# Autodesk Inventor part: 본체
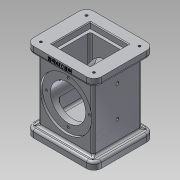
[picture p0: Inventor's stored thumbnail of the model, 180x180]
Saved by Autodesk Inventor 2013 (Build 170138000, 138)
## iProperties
Created: 2017-08
Part Number: 본체
Material: 알루미늄 6061
Document SubType Name: Modeling
Designer: Administrator
Density: 2.71 g/cm^3
Mass: 870.475 g
Surface Area: 647.043 cm^2
Volume: 321.208 cm^3
Author: Administrator
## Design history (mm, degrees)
sketch "스케치1"
  geometry: L1 (-46, -41)-(46, -41); L2 (46, -41)-(46, 41); L3 (46, 41)-(-46, 41); L4 (-46, 41)-(-46, -41); L5 (-46, -41)-(46, 41); L6 (46, -41)-(-46, 41); 1 further point
  constraints: 12 end point, 2 midpoint, 2 parallel, 1 horizontal, 1 perpendicular
  dimensions: "d0" = 92 distance of L3.end L2.end; "d1" = 82 distance of L2.end L1.end
extrude "돌출1" new body sketch "스케치1" distance "d2" = 10; taper "d3" = 0 deg
sketch "스케치2"
  geometry: L1 (-37, -33)-(37, -33); L2 (37, -33)-(37, 33); L3 (37, 33)-(-37, 33); L4 (-37, 33)-(-37, -33); L5 (-37, -33)-(37, 33); L6 (37, -33)-(-37, 33); 1 further point
  constraints: 12 end point, 2 midpoint, 2 parallel, 1 horizontal, 1 perpendicular
  dimensions: "d4" = 74 distance of L3.end L2.end; "d5" = 66 distance of L2.end L1.end
extrude "돌출2" join sketch "스케치2" distance "d6" = 88; taper "d7" = 0 deg
sketch "스케치3"
  geometry: L1 (-46, -41)-(46, -41); L2 (46, -41)-(46, 41); L3 (46, 41)-(-46, 41); L4 (-46, 41)-(-46, -41); L5 (-46, -41)-(46, 41); L6 (46, -41)-(-46, 41); 1 further point
  constraints: 12 end point, 2 midpoint, 2 parallel, 1 horizontal, 1 perpendicular
  dimensions: "d8" = 92 distance of L3.end L2.end; "d9" = 82 distance of L2.end L1.end
extrude "돌출3" join sketch "스케치3" distance "d10" = 10; taper "d11" = 0 deg
sketch "스케치4"
  geometry: L1 (-24, -24)-(24, -24); L2 (24, -24)-(24, 24); L3 (24, 24)-(-24, 24); L4 (-24, 24)-(-24, -24); L5 (-24, -24)-(24, 24); L6 (24, -24)-(-24, 24); 1 further point
  constraints: 12 end point, 2 midpoint, 2 parallel, 1 horizontal, 1 perpendicular
  dimensions: "d12" = 48 distance of L3.end L2.end; "d13" = 48 distance of L2.end L1.end
extrude "돌출4" cut sketch "스케치4" distance "d14" = 16; taper "d15" = 0 deg
sketch "스케치5"
  geometry: L1 (74, 0)-(0, 0) reference; L2 (74, 0)-(74, 88) reference; L3 (0, 88)-(74, 88) reference; L4 (0, 0)-(0, 88) reference; 1 further point
sketch "스케치6"
  geometry: L1 (-33, 10)-(33, 10) reference; L2 (-33, 10)-(-33, 98) reference; L3 (33, 98)-(-33, 98) reference; L4 (33, 10)-(33, 98) reference; L5 (-33, 89)-(-30, 89); L6 (-30, 89)-(-30, 78); L7 (-30, 78)-(30, 78); L8 (30, 78)-(30, 89); L9 (30, 89)-(33, 89); L10 (-33, 54)-(33, 54); L11 (41, 0)-(-41, 0) reference; L12 (-33, 89)-(-33, 54); L13 (33, 54)-(33, 89); L14 (33, 54)-(-33, 54); 1 further point
  constraints: 18 end point, 3 collinear, 3 perpendicular, 2 midpoint, 2 parallel, 2 point on line, 2 vertical alignment, 1 horizontal, 1 horizontal alignment
  dimensions: "d16" = 3 distance of L5.start L5.end; "d18" = 3 distance of L8.end L9.end; "d21" = 48 diameter of L7 L10; "d82" = 54 distance between parallel lines of L11 L10; "d83" = 35 distance between parallel lines of L5 L10
revolve "회전1" sketch "스케치6" stored, may be unused: angle "d22" = 90 deg
sketch "스케치7"
  geometry: L1 (-26, -26)-(26, -26); L2 (26, -26)-(26, 26); L3 (26, 26)-(-26, 26); L4 (-26, 26)-(-26, -26); L5 (-26, -26)-(26, 26); L6 (26, -26)-(-26, 26); 1 further point
  constraints: 12 end point, 2 midpoint, 2 parallel, 1 horizontal, 1 perpendicular
  dimensions: "d23" = 52 distance of L3.end L2.end; "d24" = 52 distance of L1.end L2.end
extrude "돌출5" cut sketch "스케치7" distance "d25" = 8; taper "d26" = 0 deg
sketch "스케치8"
  geometry: L1 (-22, -22)-(22, -22); L2 (22, -22)-(22, 22); L3 (22, 22)-(-22, 22); L4 (-22, 22)-(-22, -22); L5 (-22, -22)-(22, 22); L6 (22, -22)-(-22, 22); 1 further point
  constraints: 12 end point, 2 midpoint, 2 parallel, 1 horizontal, 1 perpendicular
  dimensions: "d27" = 44 distance of L3.end L2.end; "d28" = 44 distance of L2.end L1.end
extrude "돌출6" cut sketch "스케치8" distance "d29" = 74; taper "d30" = 0 deg
sketch "스케치9"
  geometry: L1 (-36, -31)-(36, -31); L2 (36, -31)-(36, 31); L3 (36, 31)-(-36, 31); L4 (-36, 31)-(-36, -31); L5 (-36, -31)-(36, 31); L6 (36, -31)-(-36, 31); 5 further points
  constraints: 12 end point, 4 coincident, 2 midpoint, 2 parallel, 1 horizontal, 1 perpendicular
  dimensions: "d31" = 72 distance of L3.end L2.end; "d32" = 62 distance of L2.end L1.end
hole "구멍1" sketch "스케치9" at (-36, 31), (36, 31), (36, -31), (-36, -31) diameter "d33" = 3.242; stored, may be unused: countersink angle "d37" = 90 deg, drill point angle "d39" = 118 deg; dims "d34" = 4, "d35" = 4, "d36" = 2, "d38" = 6
sketch "스케치10"
  geometry: L1 (-36, -31)-(36, -31); L2 (36, -31)-(36, 31); L3 (36, 31)-(-36, 31); L4 (-36, 31)-(-36, -31); L5 (-36, -31)-(36, 31); L6 (36, -31)-(-36, 31); 5 further points
  constraints: 12 end point, 4 coincident, 2 midpoint, 2 parallel, 1 horizontal, 1 perpendicular
  dimensions: "d40" = 72 distance of L3.end L2.end; "d41" = 62 distance of L2.end L1.end
hole "구멍2" sketch "스케치10" at (-36, 31), (36, 31), (36, -31), (-36, -31) diameter "d42" = 3.242; stored, may be unused: countersink angle "d46" = 90 deg, drill point angle "d48" = 118 deg; dims "d43" = 4, "d44" = 4, "d45" = 2, "d47" = 6
fillet "모깎기1" dims "d49" = 10
fillet "모깎기2" dims "d50" = 3
fillet "모깎기3" dims "d51" = 3
sketch "스케치11"
  geometry: L1 (0, 0)-(72, 0) reference; L2 (-10, 0)-(-10, -7) reference; 2 further points
  constraints: 1 other
  dimensions: "d52" = 46 distance from line of L2 point (36, -4); "d53" = 4 distance from line of L1 point (36, -4)
feature "엠보싱1" sketch "스케치11" dims "d0" = 92, "d1" = 82, "d8" = 92, "d9" = 82, "d54" = 0.5, "d55" = 0
fillet "모깎기4" dims "d56" = 3
chamfer "모따기1" distance "d57" = 1; stored, may be unused: second distance "d58" = 2, angle "d59" = 45 deg
sketch "스케치12" dims "d60" = 58
  geometry: C1 r 35 at (0, 0) reference; 3 further points
  constraints: 2 vertical alignment, 1 coincident, 2 other
hole "구멍3" sketch "스케치12" at (0, 29) diameter "d61" = 3.242; stored, may be unused: countersink angle "d65" = 90 deg, drill point angle "d67" = 118 deg; dims "d62" = 4, "d63" = 4, "d64" = 2, "d66" = 6
sketch "스케치13"
  geometry: L1 (13, -1)-(13, 61) reference; 4 further points
  constraints: 2 horizontal alignment, 1 midpoint
  dimensions: "d71" = 38 distance from line of L1 point (-25, 30); "d72" = 42 distance of point (-25, 30) point (-67, 30)
hole "구멍4" sketch "스케치13" at (-67, 30), (-25, 30) diameter "d73" = 4.134; stored, may be unused: countersink angle "d77" = 90 deg, drill point angle "d79" = 0 deg; dims "d74" = 30, "d75" = 4, "d76" = 2, "d78" = 30
fillet "모깎기5" dims "d80" = 3
fillet "모깎기6" dims "d81" = 3
node "솔리드1"
pattern_circular "원형 패턴1" dims angle "d69" = 360 deg
mirror "대칭1"
node "투영된 루프1"
